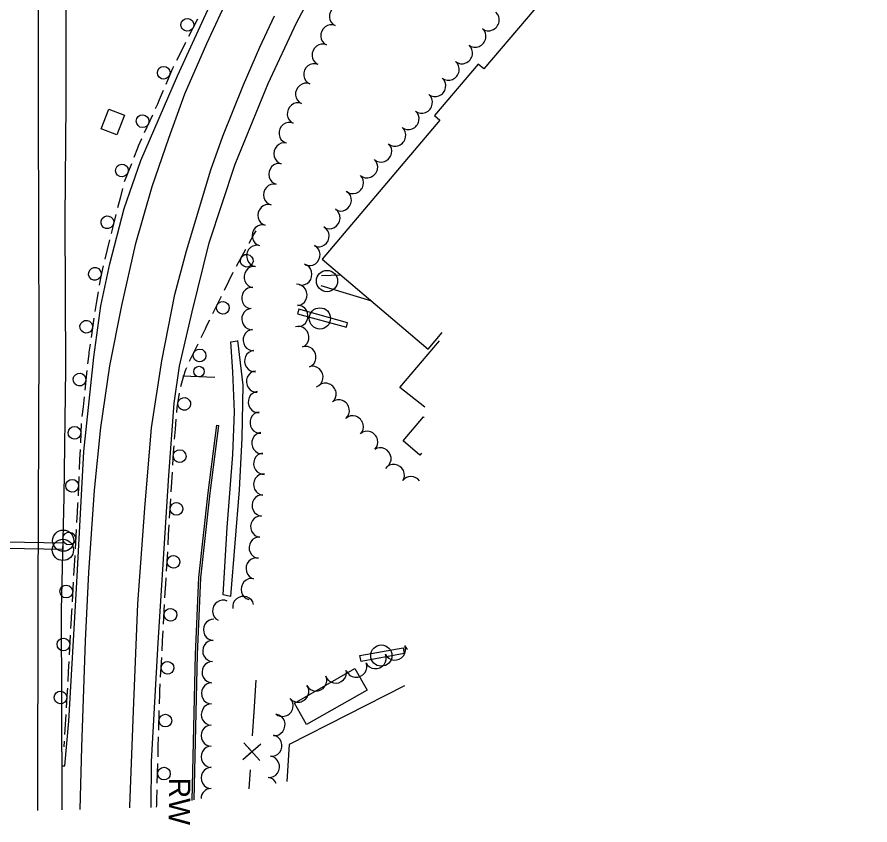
# Model space of a CAD drawing. Extents: x 1746010 to 1754829, y 655801 to 663091.
# Drawn here: x 1754021.3 to 1754423.3, y 655801.3 to 656182 of the extents above; entities that cross this region are included whole.
import ezdxf

# ---------------------------------------------------------------- set-up
doc = ezdxf.new("R2010")
doc.units = 0
for name, color, linetype in [('SURVEY - AERIAL SURVEY - Photo Control - Points - Elevations', 7, 'Continuous'), ('SURVEY - AERIAL SURVEY - Photo Control - Points - Locators', 7, 'Continuous'), ('SURVEY - AERIAL SURVEY - Photo Control - Points - Numbers', 7, 'Continuous'), ('SURVEY - AERIAL SURVEY - Photo Control with Text', 7, 'Continuous'), ('SURVEY - CENTERLINE - Existing Roads - Development', 7, 'Continuous'), ('SURVEY - CENTERLINE - Existing Roads Text', 7, 'Continuous'), ('SURVEY - CENTERLINE - Preliminary - Development', 7, 'Continuous')]:
    doc.layers.add(name, color=color, linetype=linetype)

msp = doc.modelspace()

# ---------------------------------------------------------------- linework, layer by layer
at = {"layer": 'SURVEY - AERIAL SURVEY - Photo Control - Points - Elevations'}
for points in [[(1754125.24, 656029.64), (1754127.75, 656008.57), (1754127.31, 655983.59), (1754126.06, 655959.15), (1754121.94, 655909), (1754118.51, 655909.69), (1754120.33, 655941.53), (1754123.04, 655975.9)], [(1754123.04, 655975.9), (1754123.79, 655996.01), (1754122.92, 656014.84), (1754122.09, 656028.99), (1754125.27, 656029.4)]]:
    msp.add_lwpolyline(points, dxfattribs=at)
at = {"layer": 'SURVEY - AERIAL SURVEY - Photo Control - Points - Locators'}
for points in [[(1754031.14, 655808.13), (1754031.3, 655908.75), (1754031.72, 656028.9), (1754031.37, 656137), (1754031.54, 656254.42), (1754031.6, 656339.87), (1754031.41, 656445.55), (1754032.12, 656538.49), (1754033.45, 656650.9), (1754034.71, 656754.09), (1754036.08, 656842.73), (1754037.13, 656950.3), (1754039.4, 657051.48), (1754040.61, 657114.04)], [(1754084.44, 655809.57), (1754084.69, 655831.24), (1754087.87, 655887.11), (1754090.59, 655931.61), (1754092.85, 655965.91), (1754095.39, 656000.03), (1754097.87, 656017.46), (1754103.81, 656043.12), (1754111.86, 656075.57), (1754124.11, 656112.66), (1754139.69, 656150.67), (1754153.01, 656179.28), (1754164.3, 656200.66), (1754178.54, 656224.76), (1754196.83, 656252.06), (1754209.33, 656268.76), (1754214.58, 656266.09), (1754253.38, 656323.49), (1754279.59, 656364.66), (1754324.29, 656428.69), (1754362.56, 656485.28), (1754393.05, 656531.8), (1754423.33, 656582.73)], [(1754042.35, 655829.08), (1754043.82, 655829.09), (1754045.64, 655850.26), (1754049.31, 655912.79), (1754052.69, 655977.27), (1754057.4, 656021.81), (1754060.73, 656045.88), (1754064.95, 656065.66), (1754071.74, 656091.74), (1754079.59, 656114.39), (1754096.87, 656154.39), (1754115.64, 656195.17), (1754138.21, 656238.51), (1754159.39, 656276.15), (1754180.9, 656311.04), (1754211.84, 656357.64), (1754243.66, 656406.77), (1754268.05, 656443.08), (1754301.54, 656491.51), (1754326.24, 656528.59), (1754355.07, 656574.05)], [(1754121.05, 656192.26), (1754110.53, 656169.44), (1754100.2, 656145.72), (1754092.66, 656124.81), (1754084.82, 656101.96), (1754076.98, 656074.68), (1754070.44, 656046.16), (1754064.84, 656017.61), (1754060.63, 655988.52), (1754057.68, 655959), (1754054.89, 655920.31), (1754053.44, 655888.06), (1754051.63, 655837.92), (1754050.84, 655808.64)], [(1754074.44, 655809.29), (1754074.45, 655810.03), (1754076.17, 655855.03), (1754078.15, 655905.44), (1754081.47, 655950.55), (1754084.67, 655988.4), (1754089.53, 656019.95), (1754095.6, 656051.28), (1754101.22, 656071.92), (1754112.65, 656109.96), (1754118.3, 656125.94), (1754127.96, 656150.1), (1754135.7, 656167.8), (1754142.66, 656182.53)], [(1754213.55, 655998.2), (1754201.79, 656007.45), (1754220.38, 656029.41)], [(1754203.99, 655866.88), (1754149.61, 655839.16), (1754148.44, 655821.79)]]:
    msp.add_lwpolyline(points, dxfattribs=at)
at = {"layer": 'SURVEY - AERIAL SURVEY - Photo Control - Points - Numbers'}
for points in [[(1754052.19, 657082.1), (1754050.4, 657016.97), (1754050.41, 656933.95), (1754048.92, 656857.56), (1754047.62, 656769.57), (1754047.63, 656692.19), (1754047.02, 656648.26), (1754045.2, 656574.61), (1754044.51, 656529.38), (1754044.63, 656444.15), (1754044.94, 656375.53), (1754044.42, 656301.79), (1754044.34, 656224.86), (1754044.22, 656141.35), (1754043.78, 656087.01), (1754044.06, 656016.26), (1754043.35, 655955.88), (1754042, 655902.52), (1754042.42, 655813.6), (1754042.39, 655808.41)], [(1754106.27, 656181.09), (1754102.14, 656172.87)], [(1754100.71, 656170.01), (1754098.6, 656165.81)], [(1754098.6, 656165.81), (1754096.49, 656161.61)], [(1754095.05, 656158.75), (1754094.53, 656157.72), (1754091.4, 656150.31)], [(1754090.15, 656147.36), (1754088.32, 656143.04)], [(1754088.32, 656143.04), (1754087.44, 656140.97), (1754086.42, 656138.74)], [(1754085.09, 656135.83), (1754081.25, 656127.47)], [(1754079.92, 656124.56), (1754078.39, 656121.23), (1754078.02, 656120.26)], [(1754078.02, 656120.26), (1754076.32, 656115.88)], [(1754075.17, 656112.9), (1754071.85, 656104.32)], [(1754071, 656101.23), (1754069.84, 656096.68)], [(1754069.84, 656096.68), (1754068.69, 656092.12)], [(1754067.9, 656089.02), (1754066.24, 656082.53), (1754065.66, 656080.1)], [(1754130.7, 656075.51), (1754132.97, 656079.62)], [(1754132.97, 656079.62), (1754133.92, 656081.34)], [(1754064.9, 656076.99), (1754063.8, 656072.42)], [(1754063.8, 656072.42), (1754062.69, 656067.85)], [(1754124.72, 656064.65), (1754129.16, 656072.7)], [(1754061.94, 656064.74), (1754060.56, 656059.03), (1754060.03, 656055.75)], [(1754121.15, 656057.61), (1754123.22, 656061.82)], [(1754119.07, 656053.39), (1754121.15, 656057.61)], [(1754059.51, 656052.59), (1754058.75, 656047.95)], [(1754113.59, 656042.26), (1754117.66, 656050.52)], [(1754058.75, 656047.95), (1754057.99, 656043.31)], [(1754057.52, 656040.15), (1754056.18, 656031.05)], [(1754110.11, 656035.17), (1754110.8, 656036.59), (1754112.18, 656039.39)], [(1754108.06, 656030.94), (1754110.11, 656035.17)], [(1754055.71, 656027.88), (1754055.15, 656024.07), (1754055.06, 656023.23)], [(1754102.64, 656019.79), (1754106.66, 656028.07)], [(1754055.06, 656023.23), (1754054.55, 656018.56)], [(1754054.21, 656015.38), (1754053.22, 656006.24)], [(1754099.76, 656012.46), (1754100.77, 656015.95), (1754101.24, 656016.91)], [(1754098.46, 656007.95), (1754099.76, 656012.46)], [(1754052.87, 656003.06), (1754052.37, 655998.39)], [(1754096.57, 655995.71), (1754096.76, 655997.96), (1754097.88, 656004.81)], [(1754052.37, 655998.39), (1754051.86, 655993.71)], [(1754051.57, 655990.53), (1754051.15, 655981.34)], [(1754095.92, 655987.83), (1754096.31, 655992.52)], [(1754103.83, 655812.86), (1754105.35, 655881.6), (1754106.96, 655917.9), (1754111.35, 655957.81), (1754115.52, 655989.67), (1754116.45, 655989.55)], [(1754104.77, 655813.05), (1754106.28, 655881.56), (1754107.9, 655917.81), (1754112.28, 655957.69), (1754116.45, 655989.55)], [(1754095.54, 655983.15), (1754095.92, 655987.83)], [(1754051.01, 655978.15), (1754050.79, 655973.45)], [(1754094.67, 655970.79), (1754095.03, 655976.93), (1754095.28, 655979.96)], [(1754050.79, 655973.45), (1754050.58, 655968.76)], [(1754050.43, 655965.56), (1754050.01, 655956.37)], [(1754094.2, 655962.9), (1754094.48, 655967.59)], [(1754093.93, 655958.21), (1754094.2, 655962.9)], [(1754093.2, 655945.84), (1754093.74, 655955.02)], [(1754049.87, 655953.18), (1754049.84, 655952.49), (1754049.61, 655948.48)], [(1754049.61, 655948.48), (1754049.35, 655943.79)], [(1754092.74, 655937.96), (1754093.02, 655942.65)], [(1754049.17, 655940.6), (1754048.65, 655931.42)], [(1754092.47, 655933.27), (1754092.74, 655937.96)], [(1754091.74, 655920.9), (1754092.28, 655930.07)], [(1754048.47, 655928.22), (1754048.2, 655923.53)], [(1754048.2, 655923.53), (1754047.94, 655918.84)], [(1754091.28, 655913.01), (1754091.36, 655914.38), (1754091.55, 655917.7)], [(1754047.76, 655915.64), (1754047.24, 655906.46)], [(1754091.02, 655908.32), (1754091.28, 655913.01)], [(1754090.33, 655895.94), (1754090.84, 655905.12)], [(1754047.06, 655903.26), (1754046.98, 655901.86), (1754046.8, 655898.57)], [(1754046.8, 655898.57), (1754046.54, 655893.88)], [(1754046.37, 655890.68), (1754045.86, 655881.5)], [(1754089.9, 655888.05), (1754090.16, 655892.74)], [(1754089.64, 655883.36), (1754089.9, 655888.05)], [(1754045.69, 655878.3), (1754045.43, 655873.61)], [(1754088.95, 655870.97), (1754089.46, 655880.16)], [(1754045.43, 655873.61), (1754045.18, 655868.91)], [(1754045, 655865.72), (1754044.92, 655864.31), (1754044.45, 655856.54)], [(1754088.55, 655863.08), (1754088.59, 655864.47), (1754088.77, 655867.78)], [(1754088.42, 655858.39), (1754088.55, 655863.08)], [(1754044.25, 655853.34), (1754043.97, 655848.65)], [(1754088.08, 655845.99), (1754088.33, 655855.19)], [(1754043.97, 655848.65), (1754043.68, 655843.96)], [(1754043.48, 655840.77), (1754043.32, 655838.14)], [(1754087.86, 655838.1), (1754087.99, 655842.79)], [(1754087.73, 655833.4), (1754087.86, 655838.1)], [(1754087.39, 655821), (1754087.65, 655830.2)], [(1754087.18, 655813.11), (1754087.31, 655817.81)], [(1754087.09, 655809.64), (1754087.11, 655810.6), (1754087.18, 655813.11)]]:
    msp.add_lwpolyline(points, dxfattribs=at)
for centre, start, end in [((1754101.55, 656178.36), 86.5542, 86.5402), ((1754090.45, 656155.76), 90.2768, 90.2628), ((1754080.47, 656132.93), 88.6106, 88.5966), ((1754070.73, 656109.73), 92.0683, 92.0543), ((1754063.87, 656085.34), 98.9594, 98.9454), ((1754129.55, 656067.19), 264.4225, 264.4086), ((1754057.96, 656061.01), 99.6385, 99.6245), ((1754118.3, 656045.03), 267.0631, 267.0491), ((1754053.89, 656036.08), 104.8471, 104.8332), ((1754107.33, 656022.58), 267.3437, 267.3297), ((1754050.74, 656011.17), 107.078, 107.064), ((1754100.09, 655999.74), 283.9778, 283.9639), ((1754048.37, 655986.11), 110.6378, 110.6238), ((1754097.93, 655975.15), 289.9062, 289.8922), ((1754047.23, 655961.14), 110.6378, 110.6238), ((1754096.46, 655950.21), 289.9062, 289.8922), ((1754045.92, 655936.22), 110.018, 110.004), ((1754095, 655925.26), 289.9062, 289.8922), ((1754044.51, 655911.26), 110.018, 110.004), ((1754093.58, 655900.32), 290.0787, 290.0647), ((1754043.13, 655886.3), 110.1013, 110.0873), ((1754092.19, 655875.36), 290.0787, 290.0647), ((1754041.74, 655861.35), 109.7373, 109.7233), ((1754091.2, 655850.46), 291.6859, 291.6719), ((1754090.52, 655825.47), 291.6859, 291.6719)]:
    msp.add_arc(centre, 3, start, end, dxfattribs=at)
at = {"layer": 'SURVEY - AERIAL SURVEY - Photo Control with Text'}
for p, q in [((1754173.91, 656060.45), (1754164.78, 656060.08)), ((1754164.55, 656055.57), (1754188.31, 656048.24)), ((1754167.42, 656057.57), (1754167.42, 656057.57)), ((1754164.04, 656039.97), (1754164.04, 656039.97)), ((1754114.49, 656012.21), (1754099.5, 656012.81)), ((1754043.05, 655935.21), (1754043.05, 655935.21)), ((1754042.9, 655930.86), (1754042.9, 655930.86)), ((1754193.01, 655881.06), (1754193.01, 655881.06))]:
    msp.add_line(p, q, dxfattribs=at)
for points in [[(1754153.47, 656042.23), (1754176.55, 656035.92), (1754177.12, 656038), (1754154.04, 656044.31)], [(1754042.86, 655931.09), (1753961.43, 655932.51), (1753961.49, 655935.61), (1754042.91, 655934.19)], [(1754182.92, 655881.07), (1754203.32, 655884.83), (1754203.82, 655882.13), (1754183.42, 655878.37)]]:
    msp.add_lwpolyline(points, close=True, dxfattribs=at)
for centre, radius in [((1754167.41, 656057.61), 5), ((1754164.03, 656040.01), 5), ((1754107.05, 656014.96), 2.5), ((1754043.04, 655935.25), 5), ((1754042.89, 655930.9), 5), ((1754193, 655881.1), 5)]:
    msp.add_circle(centre, radius, dxfattribs=at)
at = {"layer": 'SURVEY - CENTERLINE - Existing Roads - Development'}
for points in [[(1754331.96, 656192.68), (1754296.57, 656222.69), (1754241.36, 656157.56), (1754238.62, 656159.89), (1754218, 656135.57), (1754220.55, 656133.4), (1754165.06, 656067.95), (1754215.07, 656025.56), (1754221.68, 656033.36)], [(1754211.97, 655976.45), (1754211.18, 655975.54), (1754203.25, 655982.39), (1754212.9, 655993.56), (1754213.19, 655993.3)], [(1754133.04, 655854.59), (1754133.98, 655869.54)], [(1754132.33, 655843.23), (1754133.04, 655854.59)], [(1754135.69, 655831.6), (1754128.23, 655840.01), (1754131.97, 655835.85), (1754127.74, 655832.14), (1754136.19, 655839.47)], [(1754130.76, 655818.25), (1754131.32, 655827.19)]]:
    msp.add_lwpolyline(points, dxfattribs=at)
msp.add_lwpolyline([(1754186.29, 655864.87), (1754157.74, 655848.6), (1754151.99, 655858.7), (1754180.53, 655874.97)], close=True, dxfattribs=at)
at = {"layer": 'SURVEY - CENTERLINE - Existing Roads Text'}
for centre, major_axis, start_param, end_param in [((1754173.27, 656182.56), (2.05, 4.56), 0, 3.141593), ((1754243.78, 656180.44), (-3.15, -3.88), 0, 3.141593), ((1754169.17, 656173.44), (2.05, 4.56), 0, 3.141593), ((1754237.48, 656172.67), (-3.15, -3.88), 0, 3.141593), ((1754165.08, 656164.32), (2.05, 4.56), 0, 3.141593), ((1754231.18, 656164.9), (-3.15, -3.88), 0, 3.141593), ((1754161.18, 656155.11), (1.94, 4.61), 0, 3.141593), ((1754224.89, 656157.13), (-3.15, -3.88), 0, 3.141593), ((1754157.3, 656145.89), (1.94, 4.61), 0, 3.141593), ((1754218.59, 656149.36), (-3.15, -3.88), 0, 3.141593), ((1754153.41, 656136.67), (1.94, 4.61), 0, 3.141593), ((1754212.3, 656141.59), (-3.15, -3.88), 0, 3.141593), ((1754206, 656133.82), (-3.15, -3.88), 0, 3.141593), ((1754149.53, 656127.46), (1.94, 4.61), 0, 3.141593), ((1754199.7, 656126.05), (-3.15, -3.88), 0, 3.141593), ((1754147.07, 656117.77), (1.21, 4.85), 0, 3.141593), ((1754193.1, 656118.56), (-3.33, -3.73), 0, 3.141593), ((1754186.46, 656111.11), (-3.33, -3.73), 0, 3.141593), ((1754144.64, 656108.07), (1.21, 4.85), 0, 3.141593), ((1754179.81, 656103.66), (-3.33, -3.73), 0, 3.141593), ((1754142.22, 656098.37), (1.21, 4.85), 0, 3.141593), ((1754174.11, 656095.53), (-2.74, -4.18), 0, 3.141593), ((1754139.55, 656088.74), (1.35, 4.82), 0, 3.141593), ((1754168.74, 656087.17), (-2.62, -4.26), 0, 3.141593), ((1754136.85, 656079.12), (1.35, 4.82), 0, 3.141593), ((1754163.68, 656078.66), (-2.2, -4.49), 0, 3.141593), ((1754134.19, 656069.49), (0.58, 4.97), 0, 3.141593), ((1754159.34, 656069.8), (-2.2, -4.49), 0, 3.141593), ((1754133.02, 656059.55), (0.58, 4.97), 0, 3.141593), ((1754155.6, 656060.71), (-1.2, -4.85), 0, 3.141593), ((1754131.86, 656049.62), (0.58, 4.97), 0, 3.141593), ((1754153.28, 656051.1), (0.22, -5), 0, 3.141593), ((1754153.72, 656041.19), (0.22, -5), 0, 3.141593), ((1754131.93, 656039.69), (-0.32, 4.99), 0, 3.141593), ((1754132.56, 656029.75), (-0.32, 4.99), 0, 3.141593), ((1754154.15, 656031.28), (1.67, -4.71), 0, 3.141593), ((1754157.49, 656021.88), (1.67, -4.71), 0, 3.141593), ((1754133.24, 656019.88), (-0.44, 4.98), 0, 3.141593), ((1754160.82, 656012.47), (1.67, -4.71), 0, 3.141593), ((1754134.09, 656010.22), (-0.44, 4.98), 0, 3.141593), ((1754166.92, 656004.59), (3.12, -3.91), 0, 3.141593), ((1754134.95, 656000.56), (-0.44, 4.98), 0, 3.141593), ((1754173.15, 655996.77), (3.12, -3.91), 0, 3.141593), ((1754135.8, 655990.89), (-0.44, 4.98), 0, 3.141593), ((1754179.72, 655989.25), (3.42, -3.65), 0, 3.141593), ((1754136.65, 655981.23), (-0.44, 4.98), 0, 3.141593), ((1754186.57, 655981.96), (3.42, -3.65), 0, 3.141593), ((1754192.8, 655974.17), (2.93, -4.05), 0, 3.141593), ((1754137.5, 655971.56), (-0.44, 4.98), 0, 3.141593), ((1754199.04, 655966.44), (4.09, -2.87), 0, 3.141593), ((1754137.48, 655961.75), (0.35, 4.99), 0, 3.141593), ((1754207.22, 655960.69), (4.09, -2.87), 1.265378, 3.141593), ((1754136.79, 655951.83), (0.35, 4.99), 0, 3.141593), ((1754136.09, 655941.91), (0.35, 4.99), 0, 3.141593), ((1754135.4, 655931.98), (0.35, 4.99), 0, 3.141593), ((1754133.93, 655922.16), (1.15, 4.87), 0, 3.141593), ((1754131.64, 655912.46), (1.15, 4.87), 0, 3.141593), ((1754127.9, 655904.27), (4.91, 0.92), 0, 3.141593), ((1754118.19, 655902.28), (2.18, 4.5), 0, 3.141593), ((1754113.84, 655893.28), (0.16, 5), 0, 3.141593), ((1754113.51, 655883.29), (0.16, 5), 0, 3.141593), ((1754199.52, 655883.73), (-4.58, -2.02), 0, 3.141593), ((1754208.68, 655887.76), (-4.58, -2.02), 0, 0.41936), ((1754190.37, 655879.7), (-4.58, -2.02), 0, 3.141593), ((1754113.19, 655873.3), (0.16, 5), 0, 3.141593), ((1754181.22, 655875.67), (-4.58, -2.02), 0, 3.141593), ((1754171.64, 655872.85), (-4.8, -1.4), 0, 3.141593), ((1754162.39, 655869.17), (-4.48, -2.22), 0, 3.141593), ((1754112.89, 655863.31), (0.02, 5), 0, 3.141593), ((1754153.94, 655863.96), (-3.92, -3.1), 0, 3.141593), ((1754146.63, 655857.24), (-3.43, -3.63), 0, 3.141593), ((1754112.85, 655853.34), (0.02, 5), 0, 3.141593), ((1754142.93, 655848.46), (-0.74, -4.94), 0, 3.141593), ((1754112.82, 655843.37), (0.02, 5), 0, 3.141593), ((1754141.45, 655838.6), (-0.74, -4.94), 0, 3.141593), ((1754112.78, 655833.41), (0.02, 5), 0, 3.141593), ((1754140.28, 655828.68), (-0.54, -4.97), 0, 3.141593), ((1754112.75, 655823.44), (0.02, 5), 0, 3.141593), ((1754139.19, 655818.74), (-0.54, -4.97), 2.099789, 3.141593), ((1754112.71, 655813.47), (0.02, 5), 0, 1.52812)]:
    msp.add_ellipse(centre, major_axis=major_axis, ratio=0.940188, start_param=start_param, end_param=end_param, dxfattribs=at)
at = {"layer": 'SURVEY - CENTERLINE - Preliminary - Development'}
msp.add_line((1754066.42, 656132.56), (1754066.42, 656132.56), dxfattribs=at)
msp.add_lwpolyline([(1754068.35, 656126.45), (1754060.88, 656129.33), (1754064.49, 656138.66), (1754071.96, 656135.78), (1754068.35, 656126.45)], dxfattribs=at)

# ---------------------------------------------------------------- texts
at = {"layer": 'SURVEY - AERIAL SURVEY - Photo Control - Points - Numbers'}
msp.add_text('RW', height=10.001, rotation=269.4131, dxfattribs=at).set_placement((1754093, 655823.63))

doc.saveas('drawing.dxf')
